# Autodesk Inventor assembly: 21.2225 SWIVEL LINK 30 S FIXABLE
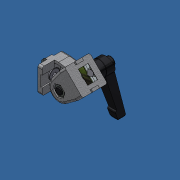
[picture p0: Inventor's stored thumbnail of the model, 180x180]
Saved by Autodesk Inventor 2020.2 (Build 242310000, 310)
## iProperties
Created: 2020-06
Part Number: 21.2225 SWIVEL LINK 30 S FIXABLE
Document SubType Name: Assembly
Designer: amoles
Author: amoles
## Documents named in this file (9)
- Y:\INVENTOR LIBRARIES\PARTS LIBRARY\30 SERIES\21.2225 SWIVEL LINK 30 S FIXABLE.iam
- Y:\INVENTOR LIBRARIES\PARTS LIBRARY\30 SERIES\SUBCOMPONENTS\21.2222 SWIVEL LINK 30 AL CASTING.ipt
- Y:\INVENTOR LIBRARIES\PARTS LIBRARY\30 SERIES\SUBCOMPONENTS\21.2222 SWIVEL LINK 30 BUSHING.dwg.ipt
- Y:\INVENTOR LIBRARIES\PARTS LIBRARY\FASTENING ELEMENTS\SCREWS CAP STAINLESS\21.1666 M8x10 Stainless.ipt
- Y:\INVENTOR LIBRARIES\PARTS LIBRARY\30 SERIES\21.1570 M8 SQUARE NUT 30 POS FXG.ipt
- Y:\INVENTOR LIBRARIES\PARTS LIBRARY\30 SERIES\SUBCOMPONENTS\21.2222 SWIVEL LINK 30 WASHER.ipt
- Y:\INVENTOR LIBRARIES\PARTS LIBRARY\FASTENING ELEMENTS\NUTS\21.1526 M8 HEX NUT.ipt
- Y:\INVENTOR LIBRARIES\PARTS LIBRARY\30 SERIES\SUBCOMPONENTS\21.2222 SWIVEL LINK 30 AL HANDLE.ipt
- 21.2222 SWIVEL LINK 30 BUSHING.dwg
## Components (10 placed, 7 different names)
1. 21.2222 SWIVEL LINK 30 AL CASTING:1 — Mate:1, Mate:2, Mate:3, Angle:1, Insert:1, Insert:3, Angle:3, Mate:7, Mate:9, Angle:5, Angle:6, Angle:7, Angle:8, Angle:9, Angle:10
2. 21.2222 SWIVEL LINK 30 AL CASTING:2 — Insert:2, Insert:4, Angle:2, Mate:5, Mate:11, Angle:4, Angle:6, Angle:7, Angle:8, Angle:9, Angle:10
3. 21.2222 SWIVEL LINK 30 BUSHING.dwg:1 — Insert:1, Insert:2, Mate:8, Mate:10
4. 21.1666 M8x10 Stainless ELH:1 — Insert:3, Mate:6
5. 21.1666 M8x10 Stainless ELH:2 — Insert:4, Mate:4
6. 21.1570 M8 SQUARE NUT 30 POS FXG:1 — Mate:4, Angle:2, Mate:5
7. 21.1570 M8 SQUARE NUT 30 POS FXG:2 — Mate:6, Angle:3, Mate:7
8. 21.2222 SWIVEL LINK 30 WASHER:1 — Mate:8, Mate:9, Insert:5
9. 21.1526 M8 HEX NUT:1 — Mate:10, Mate:11, Angle:4
10. 21.2222 SWIVEL LINK 30 AL HANDLE:1 — Insert:5, Angle:5
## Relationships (26: Mate 11, Angle 10, Insert 5)
- Mate:1: 21.2222 SWIVEL LINK 30 AL CASTING:1
- Mate:2: 21.2222 SWIVEL LINK 30 AL CASTING:1
- Mate:3: 21.2222 SWIVEL LINK 30 AL CASTING:1
- Angle:1: 21.2222 SWIVEL LINK 30 AL CASTING:1
- Insert:1: 21.2222 SWIVEL LINK 30 AL CASTING:1 ↔ 21.2222 SWIVEL LINK 30 BUSHING.dwg:1
- Insert:2: 21.2222 SWIVEL LINK 30 AL CASTING:2 ↔ 21.2222 SWIVEL LINK 30 BUSHING.dwg:1
- Insert:3: 21.2222 SWIVEL LINK 30 AL CASTING:1 ↔ 21.1666 M8x10 Stainless ELH:1
- Insert:4: 21.2222 SWIVEL LINK 30 AL CASTING:2 ↔ 21.1666 M8x10 Stainless ELH:2
- Mate:4: 21.1666 M8x10 Stainless ELH:2 ↔ 21.1570 M8 SQUARE NUT 30 POS FXG:1
- Angle:2: 21.2222 SWIVEL LINK 30 AL CASTING:2 ↔ 21.1570 M8 SQUARE NUT 30 POS FXG:1
- Mate:5: 21.2222 SWIVEL LINK 30 AL CASTING:2 ↔ 21.1570 M8 SQUARE NUT 30 POS FXG:1
- Mate:6: 21.1666 M8x10 Stainless ELH:1 ↔ 21.1570 M8 SQUARE NUT 30 POS FXG:2
- Angle:3: 21.2222 SWIVEL LINK 30 AL CASTING:1 ↔ 21.1570 M8 SQUARE NUT 30 POS FXG:2
- Mate:7: 21.2222 SWIVEL LINK 30 AL CASTING:1 ↔ 21.1570 M8 SQUARE NUT 30 POS FXG:2
- Mate:8: 21.2222 SWIVEL LINK 30 BUSHING.dwg:1 ↔ 21.2222 SWIVEL LINK 30 WASHER:1
- Mate:9: 21.2222 SWIVEL LINK 30 AL CASTING:1 ↔ 21.2222 SWIVEL LINK 30 WASHER:1
- Mate:10: 21.2222 SWIVEL LINK 30 BUSHING.dwg:1 ↔ 21.1526 M8 HEX NUT:1
- Mate:11: 21.2222 SWIVEL LINK 30 AL CASTING:2 ↔ 21.1526 M8 HEX NUT:1
- Angle:4: 21.2222 SWIVEL LINK 30 AL CASTING:2 ↔ 21.1526 M8 HEX NUT:1
- Insert:5: 21.2222 SWIVEL LINK 30 WASHER:1 ↔ 21.2222 SWIVEL LINK 30 AL HANDLE:1
- Angle:5: 21.2222 SWIVEL LINK 30 AL CASTING:1 ↔ 21.2222 SWIVEL LINK 30 AL HANDLE:1
- Angle:6: 21.2222 SWIVEL LINK 30 AL CASTING:1 ↔ 21.2222 SWIVEL LINK 30 AL CASTING:2
- Angle:7: 21.2222 SWIVEL LINK 30 AL CASTING:1 ↔ 21.2222 SWIVEL LINK 30 AL CASTING:2
- Angle:8: 21.2222 SWIVEL LINK 30 AL CASTING:1 ↔ 21.2222 SWIVEL LINK 30 AL CASTING:2
- Angle:9: 21.2222 SWIVEL LINK 30 AL CASTING:1 ↔ 21.2222 SWIVEL LINK 30 AL CASTING:2
- Angle:10: 21.2222 SWIVEL LINK 30 AL CASTING:1 ↔ 21.2222 SWIVEL LINK 30 AL CASTING:2
